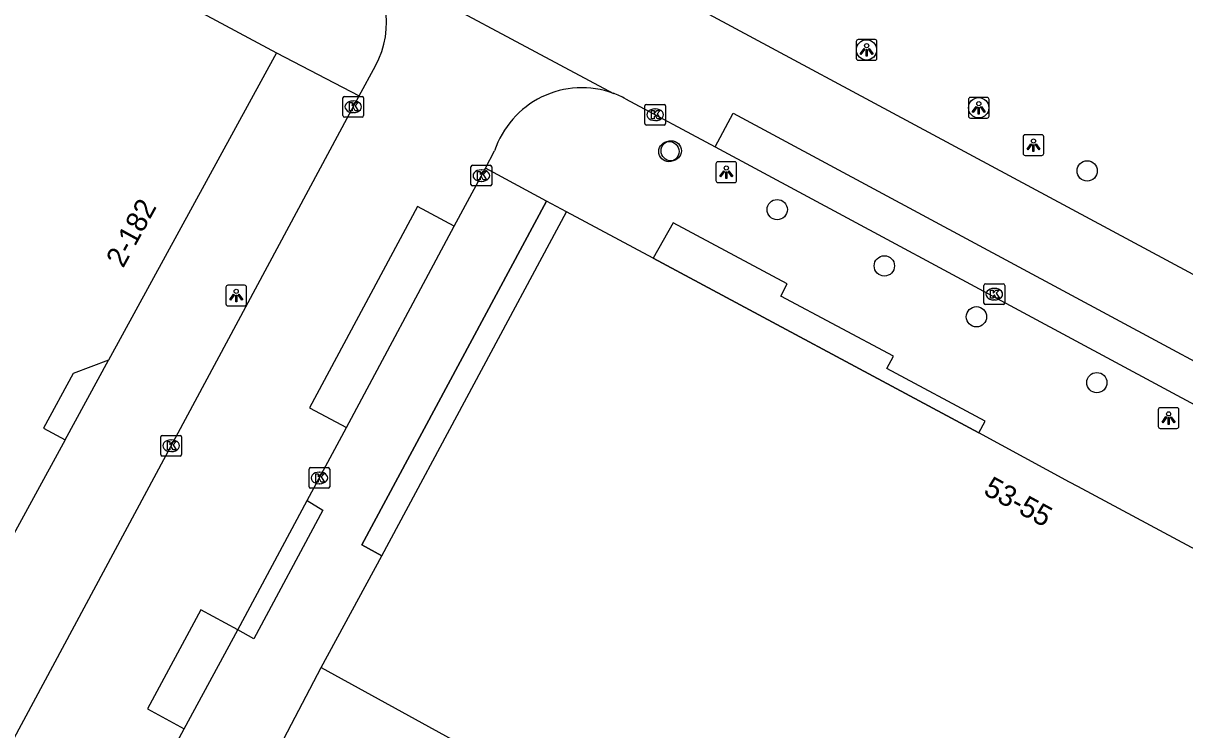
# Model space of a CAD drawing. Extents: x 159489 to 160304, y 383826 to 384530.
# Drawn here: x 159768.9 to 159824.9, y 384138.9 to 384172.9 of the extents above; entities that cross this region are included whole.
import ezdxf

# ---------------------------------------------------------------- set-up
doc = ezdxf.new("R2010")
doc.units = 0
for name, color, linetype in [('IMGEO_Boom', 7, 'Continuous'), ('IMGEO_Kolk', 7, 'Continuous'), ('IMGEO_Lichtpunt', 7, 'Continuous'), ('IMGEO_Pand', 7, 'Continuous'), ('IMGEO_Pand_nummerreeks', 7, 'Continuous'), ('IMGEO_Pand_overbouw', 7, 'Continuous'), ('IMGEO_Rijbaan_lokaal_gesloten', 7, 'Continuous'), ('IMGEO_Voetpad_open', 7, 'Continuous')]:
    doc.layers.add(name, color=color, linetype=linetype)

msp = doc.modelspace()

# ---------------------------------------------------------------- linework, layer by layer
at = {"layer": 'IMGEO_Boom'}
for centre in [(159809.519, 384171.659), (159814.925, 384168.867), (159799.993, 384166.759), (159800.105, 384166.793), (159820.155, 384165.824), (159805.216, 384163.959), (159810.378, 384161.245), (159814.817, 384158.794), (159820.622, 384155.62)]:
    msp.add_circle(centre, 0.489, dxfattribs=at)
at = {"layer": 'IMGEO_Kolk'}
for p, q in [((159784.277, 384168.489), (159784.277, 384169.341)), ((159784.352, 384169.415), (159785.204, 384169.415)), ((159784.765, 384169.195), (159784.79, 384169.195)), ((159785.278, 384169.341), (159785.278, 384168.489)), ((159784.788, 384168.635), (159784.763, 384168.635)), ((159798.832, 384168.107), (159798.832, 384168.959)), ((159798.907, 384169.033), (159799.759, 384169.033)), ((159799.32, 384168.813), (159799.345, 384168.813)), ((159799.833, 384168.959), (159799.833, 384168.107)), ((159785.204, 384168.415), (159784.352, 384168.415)), ((159799.759, 384168.033), (159798.907, 384168.033)), ((159799.343, 384168.253), (159799.318, 384168.253)), ((159790.452, 384165.172), (159790.452, 384166.024)), ((159790.527, 384166.098), (159791.379, 384166.098)), ((159790.94, 384165.878), (159790.965, 384165.878)), ((159791.453, 384166.024), (159791.453, 384165.172)), ((159790.963, 384165.318), (159790.938, 384165.318)), ((159791.379, 384165.098), (159790.527, 384165.098)), ((159815.178, 384159.457), (159815.178, 384160.309)), ((159815.253, 384160.383), (159816.105, 384160.383)), ((159815.666, 384160.163), (159815.691, 384160.163)), ((159816.179, 384160.309), (159816.179, 384159.457)), ((159815.689, 384159.603), (159815.664, 384159.603)), ((159816.105, 384159.383), (159815.253, 384159.383)), ((159775.499, 384152.152), (159775.499, 384153.004)), ((159775.574, 384153.078), (159776.426, 384153.078)), ((159775.987, 384152.858), (159776.012, 384152.858)), ((159776.5, 384153.004), (159776.5, 384152.152)), ((159776.01, 384152.298), (159775.985, 384152.298)), ((159776.426, 384152.078), (159775.574, 384152.078)), ((159782.645, 384150.599), (159782.645, 384151.451)), ((159782.72, 384151.525), (159783.572, 384151.525)), ((159783.133, 384151.305), (159783.158, 384151.305)), ((159783.646, 384151.451), (159783.646, 384150.599)), ((159783.156, 384150.745), (159783.131, 384150.745)), ((159783.572, 384150.525), (159782.72, 384150.525))]:
    msp.add_line(p, q, dxfattribs=at)
for points in [[(159784.277, 384168.489), (159784.277, 384169.341)], [(159784.352, 384169.415), (159785.204, 384169.415)], [(159784.598, 384169.115), (159784.721, 384169.115), (159784.721, 384168.964), (159784.851, 384169.115), (159785.015, 384169.115), (159784.869, 384168.964), (159785.022, 384168.715), (159784.87, 384168.715), (159784.785, 384168.879), (159784.721, 384168.812), (159784.721, 384168.715), (159784.598, 384168.715), (159784.598, 384169.115)], [(159785.278, 384169.341), (159785.278, 384168.489)], [(159798.832, 384168.107), (159798.832, 384168.959)], [(159798.907, 384169.033), (159799.759, 384169.033)], [(159799.153, 384168.733), (159799.276, 384168.733), (159799.276, 384168.582), (159799.406, 384168.733), (159799.57, 384168.733), (159799.424, 384168.582), (159799.577, 384168.333), (159799.425, 384168.333), (159799.34, 384168.497), (159799.276, 384168.43), (159799.276, 384168.333), (159799.153, 384168.333), (159799.153, 384168.733)], [(159799.833, 384168.959), (159799.833, 384168.107)], [(159785.204, 384168.415), (159784.352, 384168.415)], [(159799.759, 384168.033), (159798.907, 384168.033)], [(159790.452, 384165.172), (159790.452, 384166.024)], [(159790.527, 384166.098), (159791.379, 384166.098)], [(159790.773, 384165.798), (159790.896, 384165.798), (159790.896, 384165.647), (159791.026, 384165.798), (159791.19, 384165.798), (159791.044, 384165.647), (159791.197, 384165.398), (159791.045, 384165.398), (159790.96, 384165.562), (159790.896, 384165.495), (159790.896, 384165.398), (159790.773, 384165.398), (159790.773, 384165.798)], [(159791.453, 384166.024), (159791.453, 384165.172)], [(159791.379, 384165.098), (159790.527, 384165.098)], [(159815.178, 384159.457), (159815.178, 384160.309)], [(159815.253, 384160.383), (159816.105, 384160.383)], [(159816.179, 384160.309), (159816.179, 384159.457)], [(159815.499, 384160.083), (159815.622, 384160.083), (159815.622, 384159.932), (159815.752, 384160.083), (159815.916, 384160.083), (159815.77, 384159.932), (159815.923, 384159.683), (159815.771, 384159.683), (159815.686, 384159.847), (159815.622, 384159.78), (159815.622, 384159.683), (159815.499, 384159.683), (159815.499, 384160.083)], [(159816.105, 384159.383), (159815.253, 384159.383)], [(159775.499, 384152.152), (159775.499, 384153.004)], [(159775.574, 384153.078), (159776.426, 384153.078)], [(159776.5, 384153.004), (159776.5, 384152.152)], [(159775.82, 384152.778), (159775.943, 384152.778), (159775.943, 384152.627), (159776.073, 384152.778), (159776.237, 384152.778), (159776.091, 384152.627), (159776.244, 384152.378), (159776.092, 384152.378), (159776.007, 384152.542), (159775.943, 384152.475), (159775.943, 384152.378), (159775.82, 384152.378), (159775.82, 384152.778)], [(159776.426, 384152.078), (159775.574, 384152.078)], [(159782.645, 384150.599), (159782.645, 384151.451)], [(159782.72, 384151.525), (159783.572, 384151.525)], [(159782.966, 384151.225), (159783.089, 384151.225), (159783.089, 384151.074), (159783.219, 384151.225), (159783.383, 384151.225), (159783.237, 384151.074), (159783.39, 384150.825), (159783.238, 384150.825), (159783.153, 384150.989), (159783.089, 384150.922), (159783.089, 384150.825), (159782.966, 384150.825), (159782.966, 384151.225)], [(159783.646, 384151.451), (159783.646, 384150.599)], [(159783.572, 384150.525), (159782.72, 384150.525)]]:
    msp.add_lwpolyline(points, dxfattribs=at)
for centre, start, end in [((159784.354, 384169.339), 91.552, 178.448), ((159784.354, 384169.339), 91.552, 178.448), ((159785.202, 384169.339), 1.552, 88.448), ((159785.202, 384169.339), 1.552, 88.448), ((159798.909, 384168.957), 91.552, 178.448), ((159798.909, 384168.957), 91.552, 178.448), ((159799.757, 384168.957), 1.552, 88.448), ((159799.757, 384168.957), 1.552, 88.448), ((159784.354, 384168.491), 181.552, 268.448), ((159784.354, 384168.491), 181.552, 268.448), ((159785.202, 384168.491), 271.552, 358.448), ((159785.202, 384168.491), 271.552, 358.448), ((159798.909, 384168.109), 181.552, 268.448), ((159798.909, 384168.109), 181.552, 268.448), ((159799.757, 384168.109), 271.552, 358.448), ((159799.757, 384168.109), 271.552, 358.448), ((159790.529, 384166.022), 91.552, 178.448), ((159790.529, 384166.022), 91.552, 178.448), ((159791.377, 384166.022), 1.552, 88.448), ((159791.377, 384166.022), 1.552, 88.448), ((159790.529, 384165.174), 181.552, 268.448), ((159790.529, 384165.174), 181.552, 268.448), ((159791.377, 384165.174), 271.552, 358.448), ((159791.377, 384165.174), 271.552, 358.448), ((159815.255, 384160.307), 91.552, 178.448), ((159815.255, 384160.307), 91.552, 178.448), ((159816.103, 384160.307), 1.552, 88.448), ((159816.103, 384160.307), 1.552, 88.448), ((159815.255, 384159.459), 181.552, 268.448), ((159815.255, 384159.459), 181.552, 268.448), ((159816.103, 384159.459), 271.552, 358.448), ((159816.103, 384159.459), 271.552, 358.448), ((159775.576, 384153.002), 91.552, 178.448), ((159775.576, 384153.002), 91.552, 178.448), ((159776.424, 384153.002), 1.552, 88.448), ((159776.424, 384153.002), 1.552, 88.448), ((159775.576, 384152.154), 181.552, 268.448), ((159775.576, 384152.154), 181.552, 268.448), ((159776.424, 384152.154), 271.552, 358.448), ((159776.424, 384152.154), 271.552, 358.448), ((159782.722, 384151.449), 91.552, 178.448), ((159782.722, 384151.449), 91.552, 178.448), ((159783.57, 384151.449), 1.552, 88.448), ((159783.57, 384151.449), 1.552, 88.448), ((159782.722, 384150.601), 181.552, 268.448), ((159782.722, 384150.601), 181.552, 268.448), ((159783.57, 384150.601), 271.552, 358.448), ((159783.57, 384150.601), 271.552, 358.448)]:
    msp.add_arc(centre, 0.0765, start, end, dxfattribs=at)
for centre, major_axis, ratio, start_param, end_param in [((159784.764, 384168.915), (-0.387, 0.002), 0.722429, 4.712389, 7.853982), ((159784.789, 384168.915), (-0.39, 0.002), 0.717154, 1.570796, 4.712389), ((159799.319, 384168.533), (-0.387, 0.002), 0.722429, 4.712389, 7.853982), ((159799.344, 384168.533), (-0.39, 0.002), 0.717154, 1.570796, 4.712389), ((159790.939, 384165.598), (-0.387, 0.002), 0.722429, 4.712389, 7.853982), ((159790.964, 384165.598), (-0.39, 0.002), 0.717154, 1.570796, 4.712389), ((159815.665, 384159.883), (-0.387, 0.002), 0.722429, 4.712389, 7.853982), ((159815.69, 384159.883), (-0.39, 0.002), 0.717154, 1.570796, 4.712389), ((159775.986, 384152.578), (-0.387, 0.002), 0.722429, 4.712389, 7.853982), ((159776.011, 384152.578), (-0.39, 0.002), 0.717154, 1.570796, 4.712389), ((159783.132, 384151.025), (-0.387, 0.002), 0.722429, 4.712389, 7.853982), ((159783.157, 384151.025), (-0.39, 0.002), 0.717154, 1.570796, 4.712389)]:
    msp.add_ellipse(centre, major_axis=major_axis, ratio=ratio, start_param=start_param, end_param=end_param, dxfattribs=at)
at = {"layer": 'IMGEO_Lichtpunt'}
for p, q in [((159809.026, 384172.062), (159809.026, 384171.255)), ((159809.026, 384172.062), (159809.026, 384171.255)), ((159809.928, 384172.157), (159809.12, 384172.157)), ((159809.928, 384172.157), (159809.12, 384172.157)), ((159810.022, 384171.255), (159810.022, 384172.062)), ((159810.022, 384171.255), (159810.022, 384172.062)), ((159809.12, 384171.161), (159809.928, 384171.161)), ((159809.12, 384171.161), (159809.928, 384171.161)), ((159814.432, 384169.27), (159814.432, 384168.463)), ((159814.432, 384169.27), (159814.432, 384168.463)), ((159815.334, 384169.365), (159814.526, 384169.365)), ((159815.334, 384169.365), (159814.526, 384169.365)), ((159815.428, 384168.463), (159815.428, 384169.27)), ((159815.428, 384168.463), (159815.428, 384169.27)), ((159814.526, 384168.369), (159815.334, 384168.369)), ((159814.526, 384168.369), (159815.334, 384168.369)), ((159817.068, 384167.471), (159817.068, 384166.664)), ((159817.068, 384167.471), (159817.068, 384166.664)), ((159817.97, 384167.566), (159817.162, 384167.566)), ((159817.97, 384167.566), (159817.162, 384167.566)), ((159818.064, 384166.664), (159818.064, 384167.471)), ((159818.064, 384166.664), (159818.064, 384167.471)), ((159817.162, 384166.57), (159817.97, 384166.57)), ((159817.162, 384166.57), (159817.97, 384166.57)), ((159802.262, 384166.168), (159802.262, 384165.361)), ((159802.262, 384166.168), (159802.262, 384165.361)), ((159803.164, 384166.263), (159802.356, 384166.263)), ((159803.164, 384166.263), (159802.356, 384166.263)), ((159803.258, 384165.361), (159803.258, 384166.168)), ((159803.258, 384165.361), (159803.258, 384166.168)), ((159802.356, 384165.267), (159803.164, 384165.267)), ((159802.356, 384165.267), (159803.164, 384165.267)), ((159778.637, 384160.22), (159778.637, 384159.413)), ((159778.637, 384160.22), (159778.637, 384159.413)), ((159779.539, 384160.315), (159778.731, 384160.315)), ((159779.539, 384160.315), (159778.731, 384160.315)), ((159779.633, 384159.413), (159779.633, 384160.22)), ((159779.633, 384159.413), (159779.633, 384160.22)), ((159778.731, 384159.319), (159779.539, 384159.319)), ((159778.731, 384159.319), (159779.539, 384159.319)), ((159823.58, 384154.315), (159823.58, 384153.508)), ((159823.58, 384154.315), (159823.58, 384153.508)), ((159824.482, 384154.41), (159823.674, 384154.41)), ((159824.482, 384154.41), (159823.674, 384154.41)), ((159824.576, 384153.508), (159824.576, 384154.315)), ((159824.576, 384153.508), (159824.576, 384154.315)), ((159823.674, 384153.414), (159824.482, 384153.414)), ((159823.674, 384153.414), (159824.482, 384153.414))]:
    msp.add_line(p, q, dxfattribs=at)
for points in [[(159809.4, 384171.726), (159809.439, 384171.698), (159809.251, 384171.436), (159809.213, 384171.463), (159809.4, 384171.726)], [(159809.502, 384171.678), (159809.549, 384171.678), (159809.549, 384171.356), (159809.502, 384171.356), (159809.502, 384171.678)], [(159809.612, 384171.698), (159809.65, 384171.725), (159809.837, 384171.463), (159809.798, 384171.435), (159809.612, 384171.698)], [(159814.806, 384168.934), (159814.845, 384168.906), (159814.657, 384168.644), (159814.619, 384168.671), (159814.806, 384168.934)], [(159814.908, 384168.886), (159814.955, 384168.886), (159814.955, 384168.564), (159814.908, 384168.564), (159814.908, 384168.886)], [(159815.018, 384168.906), (159815.056, 384168.933), (159815.243, 384168.671), (159815.204, 384168.643), (159815.018, 384168.906)], [(159817.442, 384167.135), (159817.481, 384167.107), (159817.293, 384166.845), (159817.255, 384166.872), (159817.442, 384167.135)], [(159817.544, 384167.087), (159817.591, 384167.087), (159817.591, 384166.765), (159817.544, 384166.765), (159817.544, 384167.087)], [(159817.654, 384167.107), (159817.692, 384167.134), (159817.879, 384166.872), (159817.84, 384166.844), (159817.654, 384167.107)], [(159802.636, 384165.832), (159802.675, 384165.804), (159802.487, 384165.542), (159802.449, 384165.569), (159802.636, 384165.832)], [(159802.738, 384165.784), (159802.785, 384165.784), (159802.785, 384165.462), (159802.738, 384165.462), (159802.738, 384165.784)], [(159802.848, 384165.804), (159802.886, 384165.831), (159803.073, 384165.569), (159803.034, 384165.541), (159802.848, 384165.804)], [(159779.011, 384159.884), (159779.05, 384159.856), (159778.862, 384159.594), (159778.824, 384159.621), (159779.011, 384159.884)], [(159779.113, 384159.836), (159779.16, 384159.836), (159779.16, 384159.514), (159779.113, 384159.514), (159779.113, 384159.836)], [(159779.223, 384159.856), (159779.261, 384159.883), (159779.448, 384159.621), (159779.409, 384159.593), (159779.223, 384159.856)], [(159823.954, 384153.979), (159823.993, 384153.951), (159823.805, 384153.689), (159823.767, 384153.716), (159823.954, 384153.979)], [(159824.166, 384153.951), (159824.204, 384153.978), (159824.391, 384153.716), (159824.352, 384153.688), (159824.166, 384153.951)], [(159824.056, 384153.931), (159824.103, 384153.931), (159824.103, 384153.609), (159824.056, 384153.609), (159824.056, 384153.931)]]:
    msp.add_lwpolyline(points, dxfattribs=at)
for centre in [(159809.525, 384171.86), (159814.931, 384169.068), (159817.567, 384167.269), (159802.761, 384165.966), (159779.136, 384160.018), (159824.079, 384154.113)]:
    msp.add_circle(centre, 0.0994, dxfattribs=at)
for centre, start, end in [((159809.12, 384172.062), 90, 180), ((159809.12, 384172.062), 90, 180), ((159809.928, 384172.062), 0, 90), ((159809.928, 384172.062), 0, 90), ((159809.12, 384171.255), 180, 270), ((159809.12, 384171.255), 180, 270), ((159809.928, 384171.255), 270, 0), ((159809.928, 384171.255), 270, 360), ((159814.526, 384169.27), 90, 180), ((159814.526, 384169.27), 90, 180), ((159815.334, 384169.27), 0, 90), ((159815.334, 384169.27), 0, 90), ((159814.526, 384168.463), 180, 270), ((159814.526, 384168.463), 180, 270), ((159815.334, 384168.463), 270, 0), ((159815.334, 384168.463), 270, 360), ((159817.162, 384167.471), 90, 180), ((159817.162, 384167.471), 90, 180), ((159817.97, 384167.471), 0, 90), ((159817.97, 384167.471), 0, 90), ((159817.162, 384166.664), 180, 270), ((159817.162, 384166.664), 180, 270), ((159817.97, 384166.664), 270, 0), ((159817.97, 384166.664), 270, 360), ((159802.356, 384166.168), 90, 180), ((159802.356, 384166.168), 90, 180), ((159803.164, 384166.168), 0, 90), ((159803.164, 384166.168), 0, 90), ((159802.356, 384165.361), 180, 270), ((159802.356, 384165.361), 180, 270), ((159803.164, 384165.361), 270, 0), ((159803.164, 384165.361), 270, 360), ((159778.731, 384160.22), 90, 180), ((159778.731, 384160.22), 90, 180), ((159779.539, 384160.22), 0, 90), ((159779.539, 384160.22), 0, 90), ((159778.731, 384159.413), 180, 270), ((159778.731, 384159.413), 180, 270), ((159779.539, 384159.413), 270, 0), ((159779.539, 384159.413), 270, 360), ((159823.674, 384154.315), 90, 180), ((159823.674, 384154.315), 90, 180), ((159824.482, 384154.315), 0, 90), ((159824.482, 384154.315), 0, 90), ((159823.674, 384153.508), 180, 270), ((159823.674, 384153.508), 180, 270), ((159824.482, 384153.508), 270, 0), ((159824.482, 384153.508), 270, 360)]:
    msp.add_arc(centre, 0.0946, start, end, dxfattribs=at)
at = {"layer": 'IMGEO_Pand'}
for points in [[(159751.335, 384187.138), (159759.86, 384182.554), (159760.006, 384182.817), (159781.081, 384171.509)], [(159781.081, 384171.509), (159772.985, 384156.701), (159771.281, 384156.067), (159769.847, 384153.424), (159770.883, 384152.856), (159759.218, 384131.522)], [(159786.151, 384147.266), (159795.062, 384163.855)], [(159839.222, 384140.129), (159819.699, 384150.609), (159819.305, 384150.823), (159814.929, 384153.207), (159799.236, 384161.615), (159795.062, 384163.855)], [(159783.227, 384141.884), (159786.151, 384147.266)], [(159781.249, 384138.115), (159783.227, 384141.884)], [(159783.227, 384141.884), (159798.285, 384133.608)]]:
    msp.add_lwpolyline(points, dxfattribs=at)
at = {"layer": 'IMGEO_Pand_overbouw'}
for points in [[(159795.062, 384163.855), (159794.091, 384164.365), (159785.194, 384147.8), (159786.151, 384147.266)], [(159799.236, 384161.615), (159814.929, 384153.207), (159815.242, 384153.76), (159810.503, 384156.3), (159810.815, 384156.901), (159805.385, 384159.79), (159805.7, 384160.386), (159800.192, 384163.329)], [(159771.281, 384156.067), (159769.847, 384153.424), (159770.883, 384152.856), (159772.985, 384156.701)]]:
    msp.add_lwpolyline(points, close=True, dxfattribs=at)
at = {"layer": 'IMGEO_Rijbaan_lokaal_gesloten'}
for points in [[(159855.536, 384144.567), (159759.321, 384196.257)], [(159784.863, 384176.221), (159797.318, 384169.564)], [(159785.06, 384169.44), (159785.842, 384170.895)], [(159732.135, 384070.941), (159785.06, 384169.44)], [(159797.906, 384169.299), (159802.216, 384166.981)], [(159802.216, 384166.981), (159803.09, 384168.608), (159846.53, 384145.249), (159851.528, 384142.567), (159850.655, 384140.94)], [(159791.147, 384165.96), (159791.589, 384166.785)], [(159789.648, 384163.162), (159791.147, 384165.96)], [(159789.648, 384163.162), (159787.869, 384164.115), (159782.671, 384154.411), (159784.449, 384153.458)], [(159782.562, 384149.935), (159784.449, 384153.458)], [(159779.207, 384143.701), (159782.562, 384149.935)], [(159779.207, 384143.701), (159777.432, 384144.66), (159774.854, 384139.889), (159776.629, 384138.93)], [(159775.147, 384136.187), (159776.629, 384138.93)]]:
    msp.add_lwpolyline(points, dxfattribs=at)
for centre, radius, start, end in [((159782.119, 384172.964), 4.259, 330.9388, 49.8924), ((159795.799, 384165.4), 4.432, 69.962, 161.7918), ((159795.777, 384165.36), 4.478, 61.61, 69.8697)]:
    msp.add_arc(centre, radius, start, end, dxfattribs=at)
at = {"layer": 'IMGEO_Voetpad_open'}
for points in [[(159781.081, 384171.509), (159785.06, 384169.44)], [(159802.216, 384166.981), (159840.824, 384146.221)], [(159794.091, 384164.365), (159791.147, 384165.96)], [(159786.151, 384147.266), (159785.194, 384147.8), (159794.091, 384164.365)], [(159795.062, 384163.855), (159794.091, 384164.365)], [(159784.449, 384153.458), (159789.648, 384163.162)], [(159782.562, 384149.935), (159783.314, 384149.478), (159779.992, 384143.271), (159779.207, 384143.701)], [(159776.629, 384138.93), (159779.207, 384143.701)]]:
    msp.add_lwpolyline(points, dxfattribs=at)

# ---------------------------------------------------------------- texts
at = {"layer": 'IMGEO_Pand_nummerreeks'}
for s, rotation, p in [('2-182', 61.3351, (159773.684, 384161.107)), ('53-55', 331.4189, (159815.101, 384150.266))]:
    msp.add_text(s, height=1, rotation=rotation, dxfattribs=at).set_placement(p)

doc.saveas('drawing.dxf')
